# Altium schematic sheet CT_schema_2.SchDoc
size 298 x 230 mm
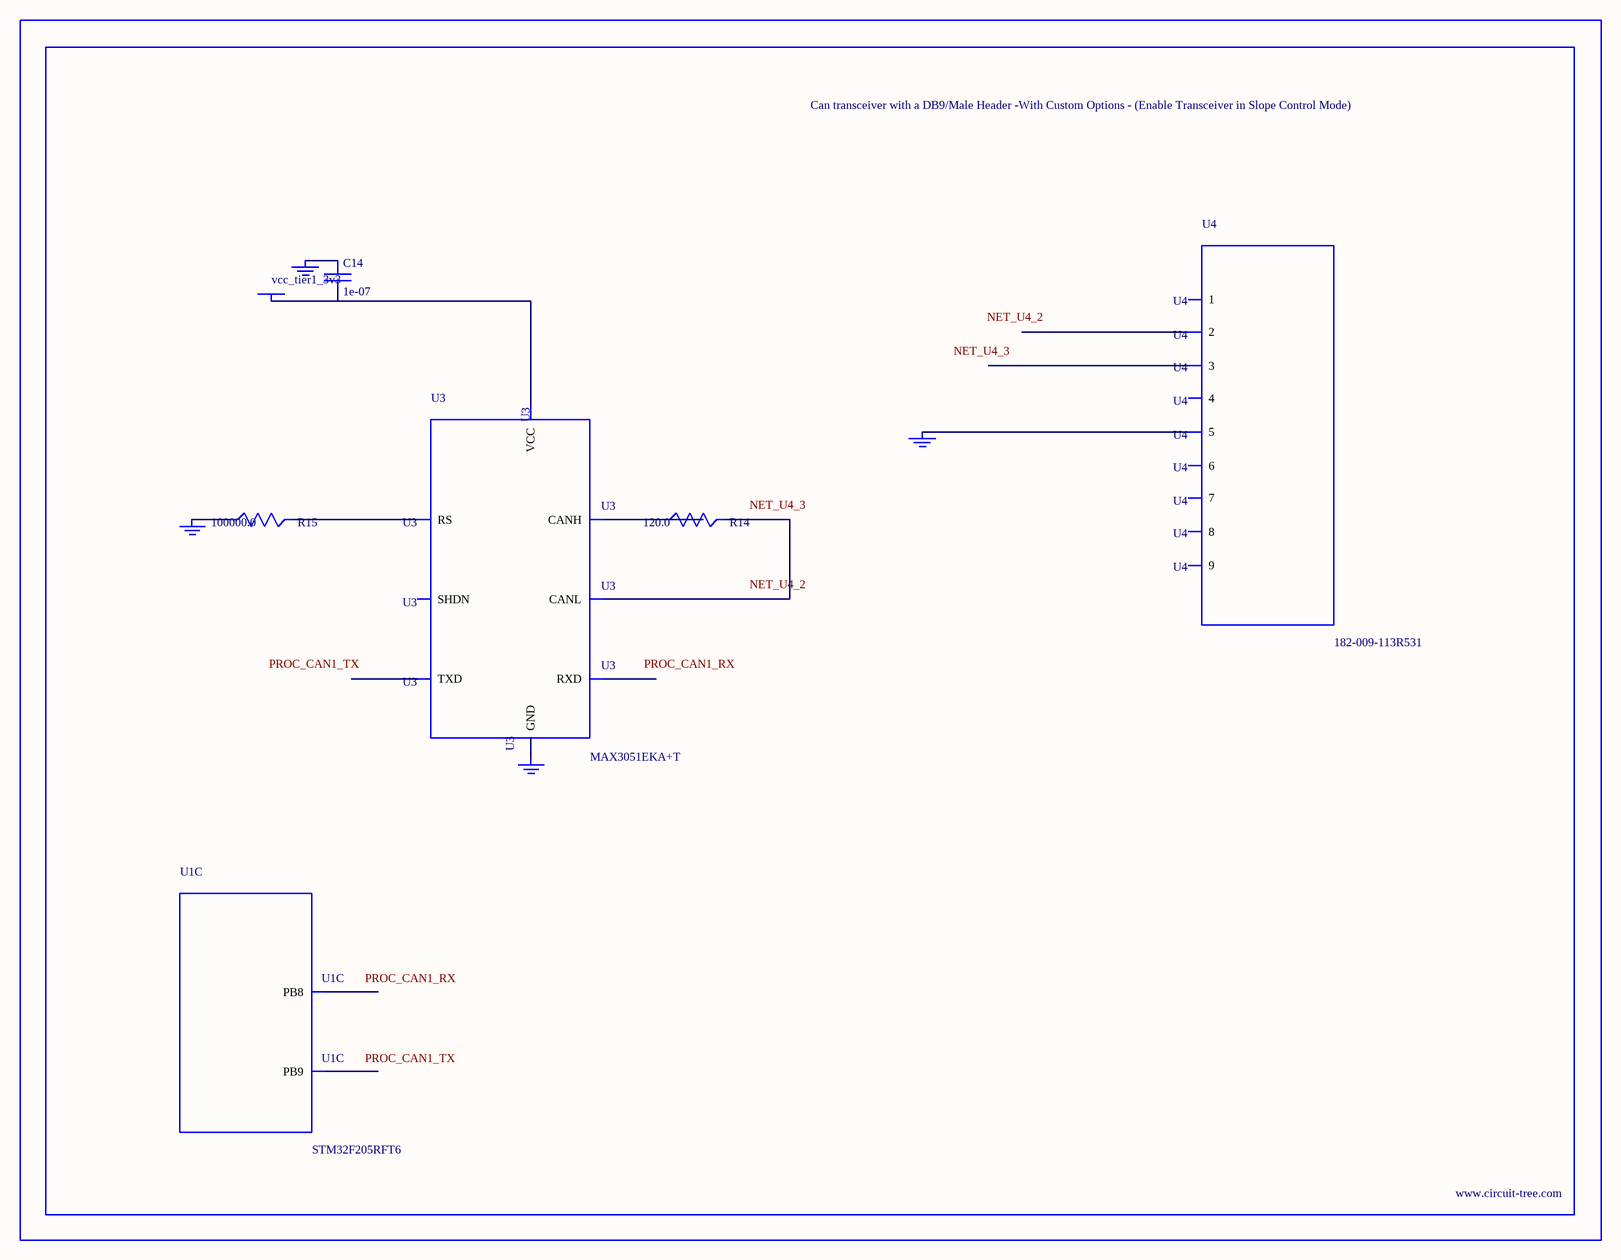
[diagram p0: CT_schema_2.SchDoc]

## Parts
BORDER1  (no value)
C14  1e-07  [C0402]
GND_INSTANCE_1_0  (no value)
GND_INSTANCE_1_1  (no value)
GND_INSTANCE_1_2  (no value)
GND_INSTANCE_1_3  (no value)
POWER_INSTANCE_1_0  vcc_tier1_3v3
R14  120.0  [R0603]
R15  100000.0  [R0603]
U1  STM32F205RFT6  [LQFP64]  (part C of 7)
U3  MAX3051EKA+T  [SOT-23-8]
U4  182-009-113R531  [182-009-MALE]

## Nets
NetC14_1: C14.1 GND_INSTANCE_1_0.0(GND)
NetC14_2: C14.2 POWER_INSTANCE_1_0.0(PWR) U3.3(VCC)
NetGND_INSTANCE_1_1_0: GND_INSTANCE_1_1.0(GND) R15.1
NetGND_INSTANCE_1_2_0: GND_INSTANCE_1_2.0(GND) U3.2(GND)
NetGND_INSTANCE_1_3_0: GND_INSTANCE_1_3.0(GND) U4.5
NetR14_1: R14.1 U3.7(CANH)
NetR14_2: R14.2 U3.6(CANL)
NetR15_2: R15.2 U3.8(RS)

Not connected (* = marked no-connect by the designer): U1 61(PB8) 62(PB9); U3 1(TXD) 4(RXD) 5(SHDN); U4 1 2 3 4 6 7 8 9

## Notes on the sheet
- Labels drawn without touching a wire or pin: NET_U4_2, NET_U4_3, PROC_CAN1_RX, PROC_CAN1_TX

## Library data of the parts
BORDER1 = BORDER_PAGE1
C14 = C0402C104K3RACTU
GND_INSTANCE_1_0-GND_INSTANCE_1_3 = GND
POWER_INSTANCE_1_0 = PWR
R14 = RC0603JR-07120RL
R15 = RC0603JR-07100KL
